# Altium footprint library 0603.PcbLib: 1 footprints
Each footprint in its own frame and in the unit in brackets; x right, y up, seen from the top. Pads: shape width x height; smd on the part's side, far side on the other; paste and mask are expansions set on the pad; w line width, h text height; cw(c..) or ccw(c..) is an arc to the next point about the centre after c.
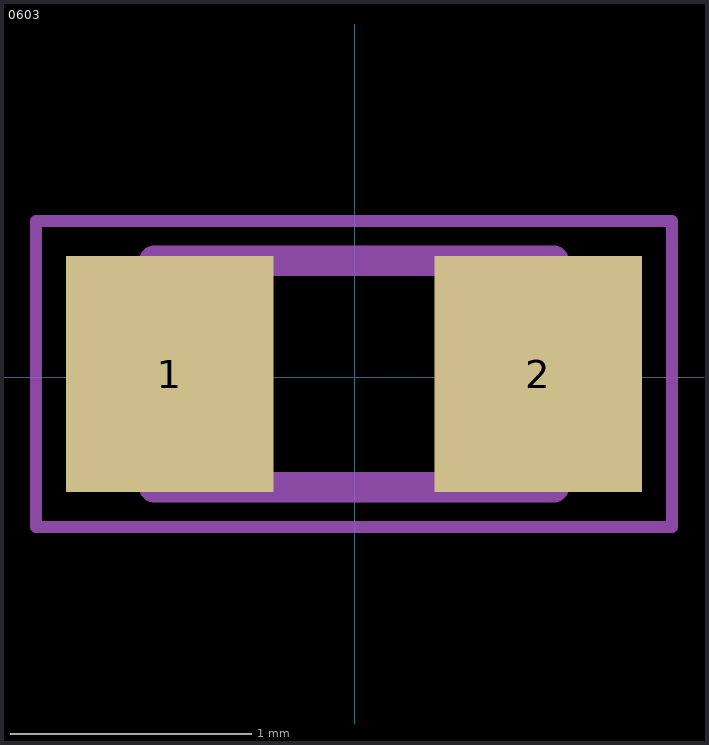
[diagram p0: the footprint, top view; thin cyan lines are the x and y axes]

## 0603 [mm]
pads (2):
  rect 0.86x0.98 smd mask+0.05: 1(-0.769,0.013) 2(0.761,0.013)
Mechanical 13:
  lines w0.127: -0.834,-0.457 -0.834,0.483 0.826,0.483 0.826,-0.457 -0.834,-0.457
Mechanical 15:
  lines w0.05: -1.325,-0.622 -1.325,0.648 1.317,0.648 1.317,-0.622 -1.325,-0.622
3D body "step_temp.STEP": height 0.55, standoff 0, extent -0.779,-0.412 0.771,0.438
